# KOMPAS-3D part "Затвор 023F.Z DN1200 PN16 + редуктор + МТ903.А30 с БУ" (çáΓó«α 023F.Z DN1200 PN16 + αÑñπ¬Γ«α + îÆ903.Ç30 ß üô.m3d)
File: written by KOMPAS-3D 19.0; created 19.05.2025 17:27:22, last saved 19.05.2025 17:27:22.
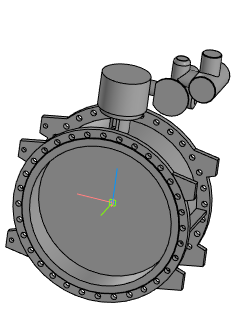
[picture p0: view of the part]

Document properties: Полное имя файла: Затвор 023F.Z DN1200 PN16 + редуктор + МТ903.А30 с БУ.a3d

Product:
- Part/product: Затвор 023F.Z DN1200 PN16 + редуктор + МТ903.А30 с БУ
    Масса: 2497.87

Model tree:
1. Операция без истории:1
